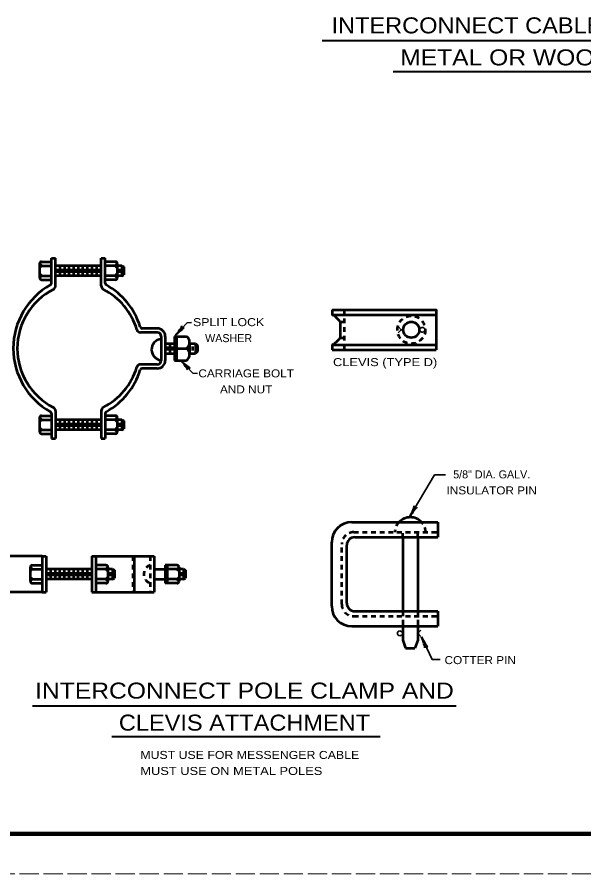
# Model space of a CAD drawing. Extents: x -368 to 312, y -34 to 406.
# Drawn here: x -221.3 to -79.7, y -34 to 180.1 of the extents above; entities that cross this region are included whole.
import ezdxf
from ezdxf.enums import TextEntityAlignment as Align

# ---------------------------------------------------------------- set-up
doc = ezdxf.new("R2010")
doc.units = 0
doc.header["$LTSCALE"] = 0.8
for name, pattern in [('LONG_DASHED', [7.5, 6, -1.5]), ('MEDIUM_DASHED', [4.5, 3, -1.5]), ('SHORT_DASHED', [2.7, 1.5, -1.2])]:
    doc.linetypes.add(name, pattern=pattern)
doc.layers.add('1', color=7, linetype='Continuous', lineweight=53)
doc.layers.add('61', color=7, linetype='Continuous', lineweight=35)

msp = doc.modelspace()

# ---------------------------------------------------------------- linework, layer by layer
at = {"layer": '1', "lineweight": 40}
for p, q in [((-145.0753, 174.1914), (-31.117, 174.1914)), ((-127.4019, 166.5048), (-47.8685, 166.5048)), ((-217.5114, 7.9801), (-111.6039, 7.9801)), ((-197.636, 0.2935), (-130.6275, 0.2935))]:
    msp.add_line(p, q, dxfattribs=at)
at = {"layer": '1'}
for p, q in [((-215.1804, 117.9422), (-215.7107, 118.4725)), ((-215.7107, 118.4422), (-215.7107, 114.9422)), ((-215.1804, 117.9422), (-215.7107, 117.4118)), ((-215.2107, 118.9422), (-212.7107, 118.9422)), ((-215.1804, 117.9422), (-212.7107, 117.9422)), ((-212.7114, 113.5901), (-212.7114, 119.7942)), ((-212.7114, 119.7942), (-211.7114, 119.7942)), ((-211.7114, 112.9182), (-211.7114, 119.7942)), ((-200.2926, 117.9422), (-211.7114, 117.9422)), ((-210.5694, 115.4422), (-210.5694, 117.9422)), ((-209.4274, 115.4422), (-209.4274, 117.9422)), ((-208.2854, 115.4422), (-208.2854, 117.9422)), ((-207.1434, 115.4422), (-207.1434, 117.9422)), ((-206.0014, 115.4422), (-206.0014, 117.9422)), ((-204.8594, 115.4422), (-204.8594, 117.9422)), ((-203.7174, 115.4422), (-203.7174, 117.9422)), ((-202.5754, 115.4422), (-202.5754, 117.9422)), ((-201.4334, 115.4422), (-201.4334, 117.9422)), ((-200.2926, 112.9182), (-200.2926, 119.7942)), ((-200.2926, 119.7942), (-199.2926, 119.7942)), ((-199.2926, 113.5901), (-199.2926, 119.7942)), ((-196.7926, 118.9422), (-199.2926, 118.9422)), ((-196.8229, 117.9422), (-199.2926, 117.9422)), ((-196.8229, 117.9422), (-196.2926, 118.4725)), ((-196.8229, 117.9422), (-196.2926, 117.4118)), ((-196.2926, 118.4422), (-196.2926, 114.9422)), ((-195.1506, 117.9422), (-196.2926, 117.9422)), ((-195.1506, 117.9422), (-195.1506, 115.4422)), ((-195.1506, 117.9422), (-194.6506, 117.6922)), ((-215.1804, 115.4422), (-215.7107, 115.9725)), ((-211.1404, 116.1922), (-211.1404, 117.1922)), ((-209.9984, 116.1922), (-209.9984, 117.1922)), ((-208.8564, 116.1922), (-208.8564, 117.1922)), ((-207.7144, 116.1922), (-207.7144, 117.1922)), ((-206.5724, 116.1922), (-206.5724, 117.1922)), ((-205.4304, 116.1922), (-205.4304, 117.1922)), ((-204.2884, 116.1922), (-204.2884, 117.1922)), ((-203.1464, 116.1922), (-203.1464, 117.1922)), ((-202.0044, 116.1922), (-202.0044, 117.1922)), ((-200.8624, 116.1922), (-200.8624, 117.1922)), ((-196.8229, 115.4422), (-196.2926, 115.9725)), ((-195.7257, 116.1922), (-195.7257, 117.1922)), ((-195.1506, 115.4422), (-194.6506, 115.6922)), ((-194.6506, 117.6922), (-194.6506, 115.6922)), ((-215.1804, 115.4422), (-215.7107, 114.9118)), ((-215.2107, 114.4422), (-212.7107, 114.4422)), ((-215.1804, 115.4422), (-212.7107, 115.4422)), ((-200.2926, 115.4422), (-211.7114, 115.4422)), ((-196.8229, 115.4422), (-199.2926, 115.4422)), ((-196.7926, 114.4422), (-199.2926, 114.4422)), ((-196.8229, 115.4422), (-196.2926, 114.9118)), ((-195.1506, 115.4422), (-196.2926, 115.4422)), ((-142.612, 106.9345), (-142.612, 105.6845)), ((-142.612, 105.6845), (-116.612, 105.6845)), ((-140.612, 103.9345), (-140.612, 99.9345)), ((-140.612, 103.9345), (-139.612, 103.9345)), ((-186.2926, 101.2942), (-190.4661, 101.2942)), ((-186.2926, 102.2942), (-190.0768, 102.2942)), ((-185.2926, 100.2942), (-185.2926, 94.2942)), ((-184.2926, 100.2942), (-184.2926, 94.2942)), ((-184.2926, 98.5442), (-182.0086, 98.5442)), ((-183.1506, 98.5442), (-183.1506, 96.0442)), ((-182.0086, 100.2942), (-182.0086, 94.2942)), ((-182.0086, 100.2942), (-179.0086, 100.2942)), ((-181.5086, 100.2942), (-181.5086, 94.2942)), ((-178.2507, 98.5442), (-176.7926, 98.5442)), ((-178.2507, 98.5442), (-178.2507, 96.0442)), ((-176.7926, 98.5442), (-176.7926, 96.0442)), ((-176.7926, 98.5442), (-176.2926, 98.0442)), ((-140.612, 99.9345), (-139.612, 99.9345)), ((-183.7216, 97.7942), (-183.7216, 96.7942)), ((-182.5796, 97.7942), (-182.5796, 96.7942)), ((-181.5086, 97.2942), (-179.0086, 97.2942)), ((-177.5247, 97.7942), (-177.5247, 96.7942)), ((-176.2926, 96.5442), (-176.7926, 96.0442)), ((-176.2926, 98.0442), (-176.2926, 96.5442)), ((-142.612, 98.1845), (-116.612, 98.1845)), ((-142.612, 98.1845), (-142.612, 96.9345)), ((-142.612, 96.9345), (-116.612, 96.9345)), ((-184.2926, 96.0442), (-182.0086, 96.0442)), ((-182.0086, 94.2942), (-179.0086, 94.2942)), ((-178.2507, 96.0442), (-176.7926, 96.0442)), ((-186.2926, 93.2942), (-190.4734, 93.2942)), ((-186.2926, 92.2942), (-190.0845, 92.2942)), ((-211.7114, 81.6703), (-211.7114, 74.7942)), ((-200.2926, 81.6952), (-200.2926, 74.7942)), ((-215.1804, 79.4822), (-215.7107, 80.0126)), ((-215.7107, 79.9822), (-215.7107, 76.4822)), ((-215.1804, 79.4822), (-215.7107, 78.9519)), ((-215.2107, 80.4822), (-212.7107, 80.4822)), ((-215.1804, 79.4822), (-212.7107, 79.4822)), ((-212.7114, 80.9984), (-212.7114, 74.7942)), ((-200.2926, 79.4822), (-211.7114, 79.4822)), ((-210.5694, 76.9822), (-210.5694, 79.4822)), ((-209.4274, 76.9822), (-209.4274, 79.4822)), ((-208.2854, 76.9822), (-208.2854, 79.4822)), ((-207.1434, 76.9822), (-207.1434, 79.4822)), ((-206.0014, 76.9822), (-206.0014, 79.4822)), ((-204.8594, 76.9822), (-204.8594, 79.4822)), ((-203.7174, 76.9822), (-203.7174, 79.4822)), ((-202.5754, 76.9822), (-202.5754, 79.4822)), ((-201.4334, 76.9822), (-201.4334, 79.4822)), ((-199.2926, 81.0287), (-199.2926, 74.7942)), ((-196.7926, 80.4822), (-199.2926, 80.4822)), ((-196.8229, 79.4822), (-199.2926, 79.4822)), ((-196.8229, 79.4822), (-196.2926, 80.0126)), ((-196.8229, 79.4822), (-196.2926, 78.9519)), ((-196.2926, 79.9822), (-196.2926, 76.4822)), ((-195.1506, 79.4822), (-196.2926, 79.4822)), ((-195.1506, 79.4822), (-195.1506, 76.9822)), ((-195.1506, 79.4822), (-194.6506, 79.2322)), ((-194.6506, 79.2322), (-194.6506, 77.2322)), ((-215.1804, 76.9822), (-215.7107, 77.5126)), ((-211.1404, 77.7322), (-211.1404, 78.7322)), ((-209.9984, 77.7322), (-209.9984, 78.7322)), ((-208.8564, 77.7322), (-208.8564, 78.7322)), ((-207.7144, 77.7322), (-207.7144, 78.7322)), ((-206.5724, 77.7322), (-206.5724, 78.7322)), ((-205.4304, 77.7322), (-205.4304, 78.7322)), ((-204.2884, 77.7322), (-204.2884, 78.7322)), ((-203.1464, 77.7322), (-203.1464, 78.7322)), ((-202.0044, 77.7322), (-202.0044, 78.7322)), ((-200.8624, 77.7322), (-200.8624, 78.7322)), ((-196.8229, 76.9822), (-196.2926, 77.5126)), ((-195.7257, 77.7322), (-195.7257, 78.7322)), ((-195.1506, 76.9822), (-194.6506, 77.2322)), ((-215.1804, 76.9822), (-215.7107, 76.4519)), ((-215.2107, 75.9822), (-212.7107, 75.9822)), ((-215.1804, 76.9822), (-212.7107, 76.9822)), ((-200.2926, 76.9822), (-211.7114, 76.9822)), ((-196.8229, 76.9822), (-199.2926, 76.9822)), ((-196.7926, 75.9822), (-199.2926, 75.9822)), ((-196.8229, 76.9822), (-196.2926, 76.4519)), ((-195.1506, 76.9822), (-196.2926, 76.9822)), ((-212.7114, 74.7942), (-211.7114, 74.7942)), ((-200.2926, 74.7942), (-199.2926, 74.7942)), ((-137.72, 53.8725), (-116.22, 53.8725)), ((-116.22, 53.8725), (-116.22, 50.1225)), ((-136.97, 50.1225), (-116.22, 50.1225)), ((-124.97, 50.1225), (-124.97, 31.6225)), ((-121.22, 50.1225), (-121.22, 31.6225)), ((-142.72, 32.8725), (-142.72, 48.8725)), ((-138.97, 33.6225), (-138.97, 48.1225)), ((-215.0302, 45.3725), (-226.2802, 45.3725)), ((-215.0302, 45.3725), (-215.0302, 36.3725)), ((-215.0302, 45.3725), (-214.0302, 45.3725)), ((-214.0302, 45.3725), (-214.0302, 36.3725)), ((-202.612, 45.3725), (-202.612, 36.3725)), ((-202.612, 45.3725), (-201.612, 45.3725)), ((-201.612, 45.3725), (-201.612, 36.3725)), ((-201.612, 45.3725), (-187.112, 45.3725)), ((-192.112, 45.3725), (-192.112, 36.3725)), ((-187.112, 45.3725), (-187.112, 36.3725)), ((-217.5302, 43.1225), (-215.0302, 43.1225)), ((-199.112, 43.1225), (-201.612, 43.1225)), ((-181.362, 43.1225), (-184.362, 43.1225)), ((-184.362, 43.1225), (-184.362, 38.6225)), ((-183.862, 43.1225), (-183.862, 38.6225)), ((-217.4998, 42.1225), (-218.0302, 42.6528)), ((-218.0302, 42.6225), (-218.0302, 39.1225)), ((-217.4998, 42.1225), (-218.0302, 41.5922)), ((-217.4998, 42.1225), (-215.0302, 42.1225)), ((-202.612, 42.1225), (-214.0308, 42.1225)), ((-213.4598, 40.3725), (-213.4598, 41.3725)), ((-212.8888, 39.6225), (-212.8888, 42.1225)), ((-212.3178, 40.3725), (-212.3178, 41.3725)), ((-211.7468, 39.6225), (-211.7468, 42.1225)), ((-211.1758, 40.3725), (-211.1758, 41.3725)), ((-210.6048, 39.6225), (-210.6048, 42.1225)), ((-210.0338, 40.3725), (-210.0338, 41.3725)), ((-209.4628, 39.6225), (-209.4628, 42.1225)), ((-208.8918, 40.3725), (-208.8918, 41.3725)), ((-208.3208, 39.6225), (-208.3208, 42.1225)), ((-207.7498, 40.3725), (-207.7498, 41.3725)), ((-207.1788, 39.6225), (-207.1788, 42.1225)), ((-206.6078, 40.3725), (-206.6078, 41.3725)), ((-206.0368, 39.6225), (-206.0368, 42.1225)), ((-205.4658, 40.3725), (-205.4658, 41.3725)), ((-204.8948, 39.6225), (-204.8948, 42.1225)), ((-204.3238, 40.3725), (-204.3238, 41.3725)), ((-203.7528, 39.6225), (-203.7528, 42.1225)), ((-203.1818, 40.3725), (-203.1818, 41.3725)), ((-199.1423, 42.1225), (-201.612, 42.1225)), ((-199.1423, 42.1225), (-198.612, 42.6528)), ((-199.1423, 42.1225), (-198.612, 41.5922)), ((-198.612, 42.6225), (-198.612, 39.1225)), ((-197.47, 42.1225), (-198.612, 42.1225)), ((-198.0451, 40.3725), (-198.0451, 41.3725)), ((-197.47, 42.1225), (-197.47, 39.6225)), ((-197.47, 42.1225), (-196.97, 41.8725)), ((-196.97, 41.8725), (-196.97, 39.8725)), ((-187.112, 42.1225), (-184.362, 42.1225)), ((-181.3923, 42.1225), (-183.862, 42.1225)), ((-181.3923, 42.1225), (-180.862, 42.6528)), ((-181.3923, 42.1225), (-180.862, 41.5922)), ((-180.862, 42.6225), (-180.862, 39.1225)), ((-179.72, 42.1225), (-180.862, 42.1225)), ((-180.2951, 40.3725), (-180.2951, 41.3725)), ((-179.72, 42.1225), (-179.72, 39.6225)), ((-179.72, 42.1225), (-179.22, 41.8725)), ((-179.22, 41.8725), (-179.22, 39.8725)), ((-217.4998, 39.6225), (-218.0302, 40.1528)), ((-217.4998, 39.6225), (-218.0302, 39.0922)), ((-217.5302, 38.6225), (-215.0302, 38.6225)), ((-217.4998, 39.6225), (-215.0302, 39.6225)), ((-202.612, 39.6225), (-214.0308, 39.6225)), ((-199.1423, 39.6225), (-201.612, 39.6225)), ((-199.112, 38.6225), (-201.612, 38.6225)), ((-199.1423, 39.6225), (-198.612, 40.1528)), ((-199.1423, 39.6225), (-198.612, 39.0922)), ((-197.47, 39.6225), (-198.612, 39.6225)), ((-197.47, 39.6225), (-196.97, 39.8725)), ((-187.112, 39.6225), (-184.362, 39.6225)), ((-181.362, 38.6225), (-184.362, 38.6225)), ((-181.3923, 39.6225), (-183.862, 39.6225)), ((-181.3923, 39.6225), (-180.862, 40.1528)), ((-181.3923, 39.6225), (-180.862, 39.0922)), ((-179.72, 39.6225), (-180.862, 39.6225)), ((-179.72, 39.6225), (-179.22, 39.8725)), ((-215.0302, 36.3725), (-226.2802, 36.3725)), ((-215.0302, 36.3725), (-214.0302, 36.3725)), ((-202.612, 36.3725), (-201.612, 36.3725)), ((-201.612, 36.3725), (-187.112, 36.3725)), ((-136.97, 31.6225), (-116.22, 31.6225)), ((-116.22, 31.6225), (-116.22, 27.8725)), ((-137.72, 27.8725), (-116.22, 27.8725)), ((-124.97, 27.8725), (-124.97, 24.3725)), ((-121.22, 27.8725), (-121.22, 24.3725)), ((-124.97, 24.3725), (-124.27, 22.3725)), ((-121.22, 24.3725), (-121.92, 22.3725)), ((-124.27, 22.3725), (-121.92, 22.3725))]:
    msp.add_line(p, q, dxfattribs=at)
at = {"layer": '1', "linetype": 'SHORT_DASHED'}
for p, q in [((-139.612, 106.9345), (-139.612, 96.9345)), ((-137.22, 51.3725), (-116.22, 51.3725)), ((-140.22, 33.3725), (-140.22, 48.3725)), ((-192.4386, 45.3725), (-192.4386, 36.3725)), ((-188.112, 45.3725), (-188.112, 36.3725)), ((-137.22, 30.3725), (-116.22, 30.3725)), ((-124.97, 31.6225), (-124.97, 27.8725)), ((-121.22, 31.6225), (-121.22, 27.8725))]:
    msp.add_line(p, q, dxfattribs=at)
at = {"layer": '1', "lineweight": 35}
for p, q in [((-125.3417, 101.9345), (-126.1373, 102.73)), ((-125.3417, 101.9345), (-126.1373, 101.1389)), ((-125.3417, 101.9345), (-124.8417, 101.9345)), ((-121.22, 26.0978), (-120.4243, 26.8933)), ((-121.22, 26.0978), (-120.4243, 25.3023))]:
    msp.add_line(p, q, dxfattribs=at)
at = {"layer": '1', "linetype": 'MEDIUM_DASHED'}
for p, q in [((-124.97, 50.1225), (-124.97, 51.1225)), ((-121.22, 50.1225), (-121.22, 51.1225))]:
    msp.add_line(p, q, dxfattribs=at)
at = {"layer": '1'}
msp.add_lwpolyline([(-142.612, 106.9345), (-116.612, 106.9345), (-116.612, 96.9345)], dxfattribs=at)
at = {"layer": '1', "lineweight": 35}
for points in [[(-181.8285, 100.523), (-178.8386, 103.7009), (-177.7173, 103.7424)], [(-180.3957, 94.2708), (-177.4058, 91.0929), (-176.2846, 91.0514)], [(-123.2249, 55.2477), (-117.0457, 65.6822), (-114.2677, 65.739)], [(-120.3221, 25.2118), (-117.6102, 19.5341), (-115.5922, 19.5341)]]:
    msp.add_lwpolyline(points, dxfattribs=at)
at = {"layer": '1', "linetype": 'SHORT_DASHED'}
msp.add_circle((-122.8235, 101.9385), 3.4836, dxfattribs=at)
at = {"layer": '1'}
msp.add_circle((-122.8417, 101.9385), 2, dxfattribs=at)
for centre, radius, start, end in [((-215.2107, 118.4422), 0.5, 90, 180), ((-196.7926, 118.4422), 0.5, 0, 90), ((-215.2107, 114.9422), 0.5, 180, 270), ((-213.2114, 113.5901), 0.5, 299.23653, 0), ((-198.7926, 113.5901), 0.5, 180, 240.76347), ((-196.7926, 114.9422), 0.5, 270, 0), ((-204.0904, 97.2942), 18.1748, 119.23653, 240.76348), ((-204.7128, 97.2942), 16.5524, 117.10997, 242.89003), ((-212.7114, 112.9182), 1, 297.10997, 0), ((-199.2926, 112.9182), 1, 180, 242.89003), ((-207.2912, 97.2942), 16.5524, 16.5506, 62.89003), ((-207.9233, 97.2942), 18.1748, 17.12844, 60.76347), ((-144.8587, 101.0989), 5.1064, 33.73114, 63.89701), ((-190.4661, 102.2943), 1, 196.5506, 270), ((-190.0768, 102.7942), 0.5, 197.12844, 270), ((-186.2926, 100.2942), 2, 0, 90), ((-186.2926, 100.2942), 1, 0, 90), ((-185.0359, 96.9588), 2.6769, 96.73046, 264.49836), ((-180.0727, 98.7942), 1.8391, 305.35262, 54.64738), ((-144.8587, 102.7977), 5.1064, 296.10299, 326.26886), ((-180.0727, 95.7942), 1.8391, 305.35262, 54.64738), ((-186.2926, 94.2942), 2, 270, 0), ((-186.2926, 94.2942), 1, 270, 0), ((-207.2912, 97.3191), 16.5524, 297.10997, 343.36481), ((-190.4735, 92.2942), 1, 90, 163.36481), ((-190.0845, 91.7942), 0.5, 90, 162.79181), ((-207.9233, 97.3191), 18.1748, 299.27052, 342.79181), ((-213.2114, 80.9984), 0.5, 0, 60.76347), ((-212.7114, 81.6703), 1, 0, 62.89003), ((-199.2926, 81.6951), 1, 117.10997, 180), ((-198.7926, 81.0287), 0.5, 119.27052, 180), ((-215.2107, 79.9822), 0.5, 90, 180), ((-196.7926, 79.9822), 0.5, 0, 90), ((-215.2107, 76.4822), 0.5, 180, 270), ((-196.7926, 76.4822), 0.5, 270, 0), ((-137.72, 48.8725), 5, 90, 180), ((-123.095, 51.2179), 3.8781, 43.15014, 136.90375), ((-136.97, 48.1225), 2, 90, 180), ((-217.5302, 42.6225), 0.5, 90, 180), ((-199.112, 42.6225), 0.5, 0, 90), ((-181.362, 42.6225), 0.5, 0, 90), ((-217.5302, 39.1225), 0.5, 180, 270), ((-199.112, 39.1225), 0.5, 270, 0), ((-181.362, 39.1225), 0.5, 270, 0), ((-137.72, 32.8725), 5, 180, 270), ((-136.97, 33.6225), 2, 180, 270)]:
    msp.add_arc(centre, radius, start, end, dxfattribs=at)
at = {"layer": '1', "lineweight": 35}
for centre, radius, start, end in [((-119.893, 101.5313), 1.0507, 108.38064, 151.10471), ((-119.898, 102.3588), 1.0433, 208.73791, 251.77673), ((-120.0709, 101.9481), 0.6002, 255.19279, 104.80721), ((-125.7168, 26.0956), 0.6002, 75.19279, 284.80721), ((-125.8947, 25.6788), 1.0507, 28.89529, 71.61936), ((-125.8897, 26.5063), 1.0433, 288.22327, 331.26209)]:
    msp.add_arc(centre, radius, start, end, dxfattribs=at)
at = {"layer": '1', "linetype": 'SHORT_DASHED'}
for centre, radius, start, end in [((-123.095, 51.2179), 3.8781, 136.80174, 177.71462), ((-123.095, 51.2179), 3.8781, 2.28538, 43.19826), ((-137.22, 48.3725), 3, 90, 180), ((-187.267, 40.8725), 2.4034, 110.5841, 249.4159), ((-137.22, 33.3725), 3, 180, 270)]:
    msp.add_arc(centre, radius, start, end, dxfattribs=at)
at = {"layer": '1', "lineweight": 40}
for centre, major_axis, ratio, start_param, end_param in [((-181.282, 101.5071), (-1.1099, -1.4076), 0.122415, 0.89635335, 3.14159265), ((-181.282, 101.5071), (-1.1099, -1.4076), 0.122415, 0.89635335, 3.14159265), ((-180.9066, 101.1941), (1.3315, 1.1589), 0.07063, 6.28230741, 8.55970261), ((-180.9066, 101.1941), (1.3315, 1.1589), 0.07063, 6.28230741, 8.55970261), ((-179.7821, 93.3098), (-1.0757, 1.3996), 0.07063, 3.14071475, 5.41810995), ((-179.4468, 93.6654), (-1.3374, 1.1936), 0.122415, 0.89635335, 3.14159265), ((-122.9066, 56.3275), (-0.7755, -1.6161), 0.122415, 0.89635335, 3.14159265), ((-122.4719, 56.1041), (-1.0461, -1.4218), 0.07063, 3.14071475, 5.41810995), ((-120.0301, 24.1095), (0.5985, -1.6606), 0.07063, 6.28230741, 8.55970261), ((-119.6025, 24.3463), (-0.9105, 1.544), 0.122415, 0.89635335, 3.14159265)]:
    msp.add_ellipse(centre, major_axis=major_axis, ratio=ratio, start_param=start_param, end_param=end_param, dxfattribs=at)
at = {"layer": '61', "lineweight": 158}
msp.add_line((301.1585, -24.0008), (-337.9015, -23.9808), dxfattribs=at)
at = {"layer": '61', "linetype": 'LONG_DASHED', "lineweight": 13}
msp.add_line((312.0985, -33.9808), (-367.9615, -34.0007), dxfattribs=at)

# ---------------------------------------------------------------- texts
at = {"layer": '1'}
for s, height, width, p in [('INTERCONNECT CABLE ATTACHMENT', 4, 1.1, (-88.0212, 175.9992)), ('METAL OR WOOD POLES', 4, 1.15, (-88.0211, 167.9992)), ('SPLIT LOCK', 2, 1.15, (-168.4776, 102.8522)), ('CLEVIS (TYPE D)', 2, 1.2, (-129.3815, 92.8608)), ('CARRIAGE BOLT', 2, 1.1, (-164.0981, 90.0527)), ('AND NUT', 2, 1.1, (-164.0981, 86.0527)), ('INSULATOR PIN', 2, 1.1, (-102.7595, 60.8108)), ('COTTER PIN', 2, 1.1, (-105.6279, 18.4079)), ('INTERCONNECT POLE CLAMP AND', 4, 1.15, (-164.5145, 9.7879)), ('CLEVIS ATTACHMENT', 4, 1.1, (-164.5144, 1.7879))]:
    msp.add_text(s, height=height, dxfattribs=dict(at, width=width)).set_placement(p, align=Align.CENTER)
for s, p in [('WASHER', (-168.4775, 98.8522)), ('5/8" DIA. GALV.', (-102.7596, 64.8108))]:
    msp.add_text(s, height=2, dxfattribs=at).set_placement(p, align=Align.CENTER)
for s, width, p in [('MUST USE FOR MESSENGER CABLE', 1.15, (-190.5377, -5.286)), ('MUST USE ON METAL POLES', 1.2, (-190.5377, -9.286))]:
    msp.add_text(s, height=2, dxfattribs=dict(at, width=width)).set_placement(p)

doc.saveas('drawing.dxf')
